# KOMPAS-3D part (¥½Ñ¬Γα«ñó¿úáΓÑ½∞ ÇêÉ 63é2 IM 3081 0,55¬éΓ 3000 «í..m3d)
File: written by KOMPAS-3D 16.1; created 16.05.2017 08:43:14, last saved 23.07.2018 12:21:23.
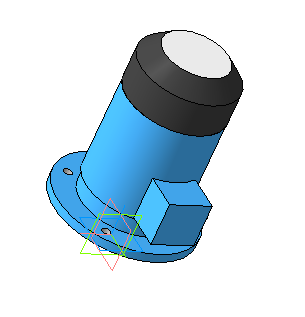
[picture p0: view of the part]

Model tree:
1. Операция без истории:1
2. Эскиз:2
3. Вырезать элемент выдавливания:1
     Расстояние 1 = 20.1
4. Эскиз:3
5. Вырезать элемент выдавливания:2  (labels: Электродвигатель  АИР 63В2 IM 3081 0,55кВт 3000об/мин IP55)
     Расстояние 1 = 4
